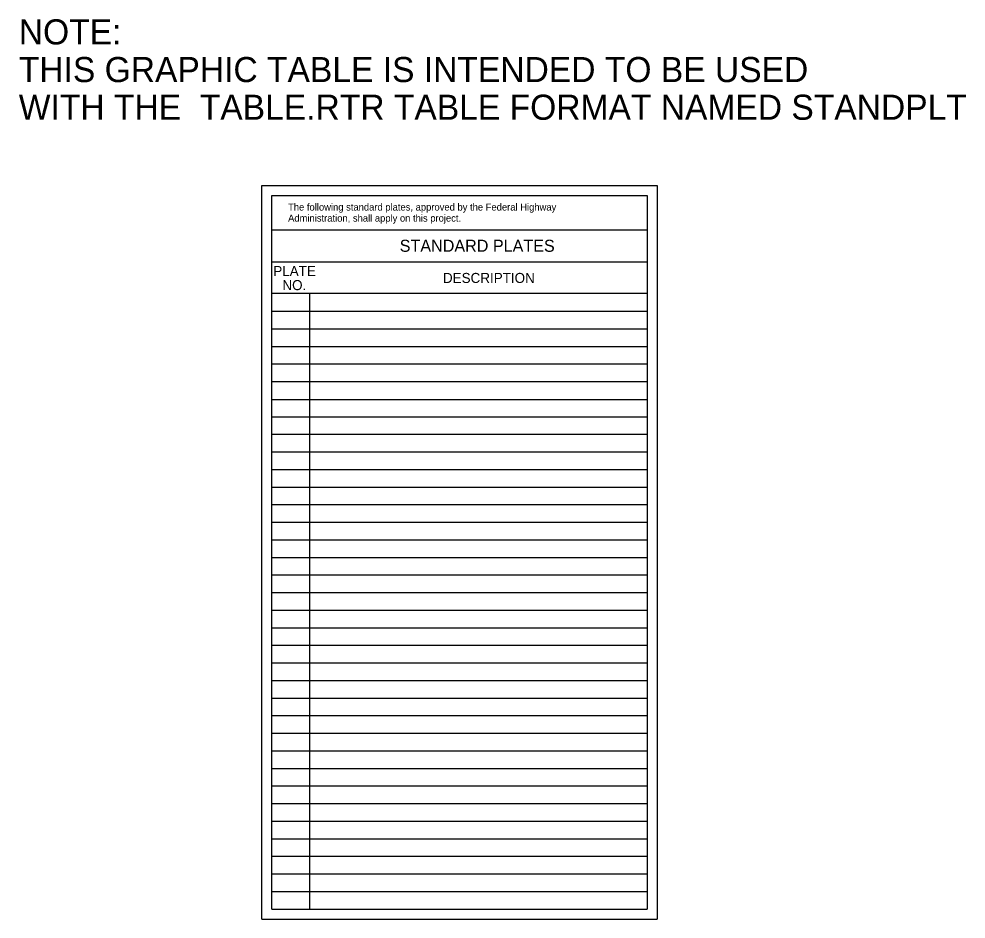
# Model space of a CAD drawing. Extents: x 5973 to 20695, y 8652 to 20433.
# Drawn here: x 19753 to 20695, y 9381 to 10277 of the extents above; entities that cross this region are included whole.
import ezdxf

# ---------------------------------------------------------------- set-up
doc = ezdxf.new("R2010")
doc.units = 0
doc.layers.add('TABULATION', color=7, linetype='Continuous')

msp = doc.modelspace()

# ---------------------------------------------------------------- linework, layer by layer
at = {"layer": 'TABULATION'}
for p, q in [((19994.26, 10111.37), (20387.85, 10111.37)), ((19994.26, 9381.16), (19994.26, 10111.37)), ((20387.85, 10111.37), (20387.85, 9381.16)), ((20004.26, 9391.16), (20004.26, 10101.37)), ((20004.26, 10101.37), (20377.85, 10101.37)), ((20377.85, 10101.37), (20377.85, 9391.16)), ((20004.26, 10067.34), (20377.85, 10067.34)), ((20004.26, 10035.31), (20377.85, 10035.31)), ((20004.26, 10004.28), (20377.85, 10004.28)), ((20042.26, 9391.16), (20042.26, 10004.28)), ((20004.26, 9986.16), (20377.85, 9986.16)), ((20004.26, 9968.66), (20377.85, 9968.66)), ((20004.26, 9951.16), (20377.85, 9951.16)), ((20004.26, 9933.66), (20377.85, 9933.66)), ((20004.26, 9916.16), (20377.85, 9916.16)), ((20004.26, 9898.44), (20377.85, 9898.44)), ((20004.26, 9881.16), (20377.85, 9881.16)), ((20004.26, 9863.66), (20377.85, 9863.66)), ((20004.26, 9846.16), (20377.85, 9846.16)), ((20004.26, 9828.66), (20377.85, 9828.66)), ((20004.26, 9811.16), (20377.85, 9811.16)), ((20004.26, 9793.66), (20377.85, 9793.66)), ((20004.26, 9776.16), (20377.85, 9776.16)), ((20004.26, 9758.66), (20377.85, 9758.66)), ((20004.26, 9741.16), (20377.85, 9741.16)), ((20004.26, 9723.66), (20377.85, 9723.66)), ((20004.26, 9706.16), (20377.85, 9706.16)), ((20004.26, 9688.66), (20377.85, 9688.66)), ((20004.26, 9671.16), (20377.85, 9671.16)), ((20004.26, 9653.66), (20377.85, 9653.66)), ((20004.26, 9636.16), (20377.85, 9636.16)), ((20004.26, 9636.16), (20377.85, 9636.16)), ((20004.26, 9618.66), (20377.85, 9618.66)), ((20004.26, 9618.66), (20377.85, 9618.66)), ((20004.26, 9601.16), (20377.85, 9601.16)), ((20004.26, 9583.66), (20377.85, 9583.66)), ((20004.26, 9583.66), (20377.85, 9583.66)), ((20004.26, 9566.16), (20377.85, 9566.16)), ((20004.26, 9548.66), (20377.85, 9548.66)), ((20004.26, 9531.16), (20377.85, 9531.16)), ((20004.26, 9531.16), (20377.85, 9531.16)), ((20004.26, 9513.66), (20377.85, 9513.66)), ((20004.26, 9496.16), (20377.85, 9496.16)), ((20004.26, 9478.66), (20377.85, 9478.66)), ((20004.26, 9478.66), (20377.85, 9478.66)), ((20004.26, 9478.66), (20377.85, 9478.66)), ((20004.26, 9461.16), (20377.85, 9461.16)), ((20004.26, 9443.66), (20377.85, 9443.66)), ((20004.26, 9426.16), (20377.85, 9426.16)), ((20004.26, 9408.66), (20377.85, 9408.66)), ((20004.26, 9391.16), (20377.85, 9391.16)), ((20004.26, 9391.16), (20377.85, 9391.16)), ((20004.26, 9391.16), (20377.85, 9391.16)), ((20004.26, 9391.16), (20377.85, 9391.16)), ((20004.26, 9391.16), (20377.85, 9391.16)), ((19994.26, 9381.16), (20387.85, 9381.16))]:
    msp.add_line(p, q, dxfattribs=at)

# ---------------------------------------------------------------- texts
for s, height, p in [('NOTE:', 25, (19752.5, 10251.72)), ('THIS GRAPHIC TABLE IS INTENDED TO BE USED', 25, (19752.5, 10214.22)), ('WITH THE  TABLE.RTR TABLE FORMAT NAMED STANDPLT', 25, (19752.5, 10176.72)), ('The following standard plates, approved by the Federal Highway ', 7, (20020.52, 10086.36)), ('Administration, shall apply on this project.', 7, (20020.52, 10075.36)), ('STANDARD PLATES', 12, (20131.64, 10045.32)), ('PLATE', 10, (20005.8, 10021.16)), ('DESCRIPTION', 10, (20174.68, 10014.29)), ('NO.', 10, (20014.87, 10007.16))]:
    msp.add_text(s, height=height, dxfattribs=at).set_placement(p)

doc.saveas('drawing.dxf')
